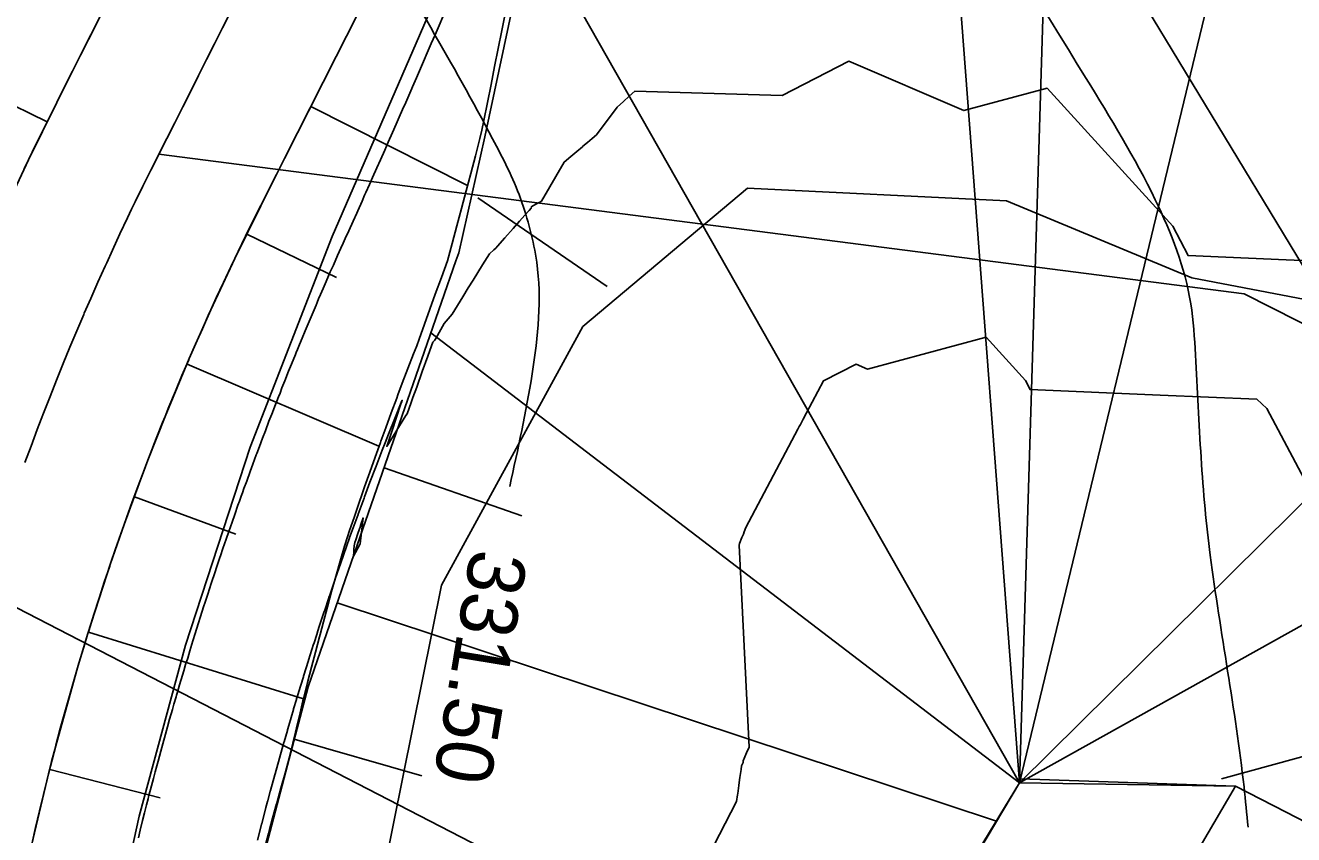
# Model space of a CAD drawing. Extents: x -564037 to -563827, y -1163561 to -1163412.
# Drawn here: x -563863.65 to -563852.55, y -1163500.35 to -1163493.27 of the extents above; entities that cross this region are included whole.
import ezdxf

# ---------------------------------------------------------------- set-up
doc = ezdxf.new("R2010")
doc.units = 0
for name, color, linetype in [('5', 7, 'Continuous'), ('_popis staničení PH4', 7, 'Continuous'), ('Default', 7, 'Continuous'), ('Line', 7, 'Continuous'), ('Vrstva 24', 7, 'Continuous'), ('Vrstva 25', 7, 'Continuous'), ('Vrstva 26', 7, 'Continuous')]:
    doc.layers.add(name, color=color, linetype=linetype)

msp = doc.modelspace()

# ---------------------------------------------------------------- linework, layer by layer
for points in [[(-563865.785, -1163501.206), (-563865.619, -1163500.343), (-563865.574, -1163500.129), (-563865.385, -1163499.33), (-563865.317, -1163499.063), (-563865.111, -1163498.327), (-563865.015, -1163498.009), (-563864.797, -1163497.335), (-563864.669, -1163496.968), (-563864.528, -1163496.58), (-563864.443, -1163496.357), (-563864.28, -1163495.943), (-563864.051, -1163495.394), (-563863.848, -1163494.935), (-563863.62, -1163494.448), (-563863.373, -1163493.946), (-563863.165, -1163493.533), (-563862.713, -1163492.641), (-563862.262, -1163491.749), (-563861.987, -1163491.206), (-563861.81, -1163490.857), (-563861.359, -1163489.964), (-563861.279, -1163489.807)], [(-563863.62, -1163500.557), (-563863.446, -1163499.819), (-563863.383, -1163499.573), (-563863.193, -1163498.893), (-563863.104, -1163498.599), (-563862.903, -1163497.978), (-563862.785, -1163497.638), (-563862.654, -1163497.28), (-563862.576, -1163497.075), (-563862.426, -1163496.692), (-563862.214, -1163496.186), (-563862.026, -1163495.761), (-563861.817, -1163495.312), (-563861.589, -1163494.849), (-563861.38, -1163494.436), (-563860.928, -1163493.544), (-563860.477, -1163492.652), (-563860.202, -1163492.109), (-563860.026, -1163491.76), (-563859.574, -1163490.867), (-563859.495, -1163490.71)], [(-563863.653, -1163497.097), (-563863.599, -1163496.952), (-563863.545, -1163496.807), (-563863.51, -1163496.716), (-563863.489, -1163496.663), (-563863.433, -1163496.518), (-563863.376, -1163496.374), (-563863.353, -1163496.317), (-563863.318, -1163496.231), (-563863.259, -1163496.088), (-563863.199, -1163495.945), (-563863.138, -1163495.802), (-563863.133, -1163495.79), (-563863.076, -1163495.66), (-563863.014, -1163495.519), (-563862.95, -1163495.377), (-563862.937, -1163495.348), (-563862.886, -1163495.237), (-563862.821, -1163495.096), (-563862.755, -1163494.956), (-563862.719, -1163494.88), (-563862.688, -1163494.816), (-563862.62, -1163494.677), (-563862.552, -1163494.538), (-563862.482, -1163494.4), (-563862.481, -1163494.397), (-563862.412, -1163494.262), (-563862.342, -1163494.123), (-563862.272, -1163493.985), (-563862.202, -1163493.847), (-563862.133, -1163493.709), (-563862.063, -1163493.571), (-563861.993, -1163493.433), (-563861.923, -1163493.294), (-563861.853, -1163493.156)], [(-563863.593, -1163500.434), (-563863.56, -1163500.289), (-563863.526, -1163500.144), (-563863.491, -1163500), (-563863.455, -1163499.856), (-563863.446, -1163499.819), (-563863.419, -1163499.711), (-563863.383, -1163499.573), (-563863.381, -1163499.568), (-563863.343, -1163499.424), (-563863.304, -1163499.281), (-563863.264, -1163499.137), (-563863.223, -1163498.995), (-563863.193, -1163498.893), (-563863.181, -1163498.852), (-563863.138, -1163498.71), (-563863.104, -1163498.599), (-563863.094, -1163498.567), (-563863.05, -1163498.426), (-563863.004, -1163498.284), (-563862.958, -1163498.143), (-563862.911, -1163498.002), (-563862.903, -1163497.978), (-563862.863, -1163497.861), (-563862.814, -1163497.721), (-563862.785, -1163497.638), (-563862.764, -1163497.581), (-563862.714, -1163497.441), (-563862.662, -1163497.301), (-563862.61, -1163497.162), (-563862.576, -1163497.075), (-563862.557, -1163497.023), (-563862.503, -1163496.885), (-563862.448, -1163496.747), (-563862.426, -1163496.692), (-563862.392, -1163496.609), (-563862.335, -1163496.472), (-563862.278, -1163496.334), (-563862.219, -1163496.198), (-563862.214, -1163496.186), (-563862.16, -1163496.061), (-563862.1, -1163495.925), (-563862.039, -1163495.79), (-563862.026, -1163495.761), (-563861.978, -1163495.654), (-563861.915, -1163495.52), (-563861.852, -1163495.385), (-563861.817, -1163495.312), (-563861.787, -1163495.251), (-563861.722, -1163495.117), (-563861.657, -1163494.984), (-563861.59, -1163494.851), (-563861.589, -1163494.849), (-563861.52, -1163494.713), (-563861.45, -1163494.575), (-563861.38, -1163494.436), (-563861.31, -1163494.299), (-563861.24, -1163494.16), (-563861.17, -1163494.022), (-563861.1, -1163493.884), (-563861.031, -1163493.746), (-563860.961, -1163493.608), (-563860.928, -1163493.544), (-563860.891, -1163493.47), (-563860.821, -1163493.331), (-563860.751, -1163493.193)], [(-563861.556, -1163500.472), (-563861.521, -1163500.34), (-563861.512, -1163500.306), (-563861.485, -1163500.208), (-563861.45, -1163500.081), (-563861.449, -1163500.077), (-563861.412, -1163499.946), (-563861.374, -1163499.815), (-563861.34, -1163499.683), (-563861.309, -1163499.55), (-563861.286, -1163499.455), (-563861.277, -1163499.417), (-563861.245, -1163499.285), (-563861.219, -1163499.182), (-563861.212, -1163499.152), (-563861.179, -1163499.019), (-563861.145, -1163498.887), (-563861.111, -1163498.754), (-563861.076, -1163498.622), (-563861.07, -1163498.599), (-563861.041, -1163498.489), (-563861.005, -1163498.357), (-563860.984, -1163498.279), (-563860.969, -1163498.225), (-563860.932, -1163498.092), (-563860.895, -1163497.96), (-563860.857, -1163497.828), (-563860.83, -1163497.746), (-563860.814, -1163497.698), (-563860.769, -1163497.568), (-563860.725, -1163497.438), (-563860.707, -1163497.386), (-563860.68, -1163497.308), (-563860.634, -1163497.179), (-563860.588, -1163497.049), (-563860.541, -1163496.92), (-563860.537, -1163496.909), (-563860.494, -1163496.791), (-563860.446, -1163496.661), (-563860.398, -1163496.532), (-563860.388, -1163496.505), (-563860.35, -1163496.403), (-563860.301, -1163496.274), (-563860.251, -1163496.146), (-563860.224, -1163496.075), (-563860.201, -1163496.017), (-563860.155, -1163495.886), (-563860.109, -1163495.755), (-563860.062, -1163495.624), (-563860.061, -1163495.622), (-563860.008, -1163495.478), (-563859.954, -1163495.332), (-563859.913, -1163495.179), (-563859.872, -1163495.026), (-563859.831, -1163494.873), (-563859.791, -1163494.72), (-563859.751, -1163494.567), (-563859.71, -1163494.414), (-563859.671, -1163494.26), (-563859.655, -1163494.189), (-563859.637, -1163494.104), (-563859.605, -1163493.946), (-563859.573, -1163493.789), (-563859.542, -1163493.631), (-563859.51, -1163493.474), (-563859.479, -1163493.316), (-563859.451, -1163493.171)], [(-563863.658, -1163494.527), (-563863.62, -1163494.448), (-563863.589, -1163494.382), (-563863.518, -1163494.237), (-563863.447, -1163494.092), (-563863.374, -1163493.948), (-563863.373, -1163493.946), (-563863.305, -1163493.81), (-563863.235, -1163493.672), (-563863.165, -1163493.533), (-563863.095, -1163493.396), (-563863.025, -1163493.257)], [(-563851.978, -1163495.349), (-563852.615, -1163495.322), (-563853.472, -1163495.285), (-563853.605, -1163495.027), (-563854.706, -1163493.822), (-563855.435, -1163494.017), (-563856.443, -1163493.586), (-563857.024, -1163493.885), (-563858.314, -1163493.847), (-563858.363, -1163493.892), (-563858.414, -1163493.938), (-563858.468, -1163493.988), (-563858.651, -1163494.229), (-563858.689, -1163494.261), (-563858.73, -1163494.296), (-563858.769, -1163494.329), (-563858.774, -1163494.333), (-563858.822, -1163494.374), (-563858.875, -1163494.418), (-563858.933, -1163494.467), (-563859.131, -1163494.809), (-563859.152, -1163494.82), (-563859.176, -1163494.834), (-563859.201, -1163494.847), (-563859.208, -1163494.851), (-563859.22, -1163494.858), (-563859.223, -1163494.872), (-563859.239, -1163494.89), (-563859.277, -1163494.933), (-563859.323, -1163494.985), (-563859.38, -1163495.049), (-563859.452, -1163495.13), (-563859.516, -1163495.202), (-563859.532, -1163495.22), (-563859.55, -1163495.236), (-563859.588, -1163495.27), (-563859.647, -1163495.365), (-563859.731, -1163495.502), (-563859.772, -1163495.568), (-563859.819, -1163495.646), (-563859.914, -1163495.799), (-563859.984, -1163495.881), (-563860.055, -1163496.01), (-563860.068, -1163496.027), (-563860.083, -1163496.044), (-563860.108, -1163496.116), (-563860.127, -1163496.166), (-563860.175, -1163496.301), (-563860.224, -1163496.436), (-563860.257, -1163496.528), (-563860.272, -1163496.571), (-563860.308, -1163496.67), (-563860.318, -1163496.685), (-563860.486, -1163496.955), (-563860.463, -1163496.887), (-563860.451, -1163496.852), (-563860.436, -1163496.807), (-563860.403, -1163496.707), (-563860.359, -1163496.574), (-563860.358, -1163496.571), (-563860.351, -1163496.551), (-563860.359, -1163496.571), (-563860.359, -1163496.571), (-563860.416, -1163496.71), (-563860.416, -1163496.71), (-563860.471, -1163496.849), (-563860.471, -1163496.849), (-563860.5, -1163496.924), (-563860.501, -1163496.925), (-563860.525, -1163496.989), (-563860.526, -1163496.989), (-563860.579, -1163497.128), (-563860.58, -1163497.129), (-563860.633, -1163497.268), (-563860.633, -1163497.269), (-563860.681, -1163497.397), (-563860.681, -1163497.397), (-563860.685, -1163497.409), (-563860.685, -1163497.409), (-563860.737, -1163497.549), (-563860.737, -1163497.55), (-563860.788, -1163497.69), (-563860.788, -1163497.69), (-563860.811, -1163497.753), (-563860.811, -1163497.754), (-563860.838, -1163497.831), (-563860.838, -1163497.832), (-563860.888, -1163497.972), (-563860.888, -1163497.973), (-563860.936, -1163498.113), (-563860.937, -1163498.115), (-563860.985, -1163498.255), (-563860.985, -1163498.255), (-563860.992, -1163498.276), (-563860.993, -1163498.279), (-563861.032, -1163498.397), (-563861.033, -1163498.4), (-563861.079, -1163498.539), (-563861.079, -1163498.54), (-563861.095, -1163498.59), (-563861.096, -1163498.593), (-563861.125, -1163498.681), (-563861.126, -1163498.685), (-563861.17, -1163498.824), (-563861.171, -1163498.828), (-563861.214, -1163498.966), (-563861.216, -1163498.971), (-563861.258, -1163499.109), (-563861.259, -1163499.111), (-563861.275, -1163499.164), (-563861.276, -1163499.168), (-563861.301, -1163499.252), (-563861.303, -1163499.258), (-563861.343, -1163499.396), (-563861.344, -1163499.397), (-563861.355, -1163499.435), (-563861.356, -1163499.439), (-563861.385, -1163499.539), (-563861.387, -1163499.546), (-563861.426, -1163499.683), (-563861.464, -1163499.82), (-563861.466, -1163499.827), (-563861.504, -1163499.964), (-563861.505, -1163499.971), (-563861.528, -1163500.056), (-563861.529, -1163500.061), (-563861.543, -1163500.113), (-563861.544, -1163500.116), (-563861.58, -1163500.254), (-563861.582, -1163500.26), (-563861.589, -1163500.286), (-563861.589, -1163500.287), (-563861.618, -1163500.4)], [(-563851.082, -1163505.728), (-563849.948, -1163501.531), (-563849.628, -1163500.347), (-563850.165, -1163499.681), (-563852.128, -1163495.731), (-563853.44, -1163495.48), (-563855.061, -1163494.806), (-563857.328, -1163494.696), (-563858.771, -1163495.906), (-563860.007, -1163498.17), (-563860.512, -1163500.673), (-563860.896, -1163502.23)], [(-563859.058, -1163503.231), (-563857.424, -1163500.06), (-563857.416, -1163500.003), (-563857.414, -1163499.991), (-563857.404, -1163499.921), (-563857.401, -1163499.894), (-563857.395, -1163499.851), (-563857.385, -1163499.781), (-563857.38, -1163499.748), (-563857.366, -1163499.72), (-563857.367, -1163499.709), (-563857.367, -1163499.705), (-563857.337, -1163499.637), (-563857.314, -1163499.585), (-563857.403, -1163497.819), (-563857.398, -1163497.805), (-563857.377, -1163497.753), (-563857.365, -1163497.722), (-563857.357, -1163497.702), (-563857.342, -1163497.665), (-563856.887, -1163496.804), (-563856.887, -1163496.803), (-563856.885, -1163496.799), (-563856.875, -1163496.781), (-563856.866, -1163496.763), (-563856.86, -1163496.752), (-563856.856, -1163496.745), (-563856.847, -1163496.728), (-563856.842, -1163496.718), (-563856.812, -1163496.661), (-563856.664, -1163496.381), (-563856.379, -1163496.234), (-563856.277, -1163496.278), (-563855.24, -1163496), (-563854.896, -1163496.377), (-563854.855, -1163496.458), (-563853.717, -1163496.506), (-563852.871, -1163496.541), (-563852.783, -1163496.623), (-563852.407, -1163497.332)], [(-563855.984, -1163506.959), (-563857.031, -1163504.7), (-563857.031, -1163504.7), (-563856.418, -1163503.019), (-563856.418, -1163503.019), (-563855.805, -1163501.338), (-563854.949, -1163499.897), (-563853.059, -1163499.927), (-563853.059, -1163499.927), (-563852.615, -1163500.156), (-563851.726, -1163500.614), (-563850.837, -1163501.073), (-563850.62, -1163501.184), (-563850.566, -1163501.212), (-563849.948, -1163501.531), (-563849.059, -1163501.989), (-563848.632, -1163503.326), (-563848.683, -1163504.7), (-563848.816, -1163505.479), (-563849.057, -1163506.682), (-563849.057, -1163506.682)], [(-563854.345, -1163502.122), (-563853.059, -1163499.927), (-563853.059, -1163499.927), (-563854.941, -1163499.862), (-563854.943, -1163499.866), (-563854.945, -1163499.871), (-563854.945, -1163499.872), (-563854.945, -1163499.872), (-563854.946, -1163499.874), (-563854.947, -1163499.877), (-563854.947, -1163499.882), (-563854.948, -1163499.885), (-563854.948, -1163499.887), (-563854.949, -1163499.892), (-563854.949, -1163499.893), (-563854.949, -1163499.897), (-563855.795, -1163501.288)]]:
    msp.add_lwpolyline(points)
for points in [[(-563864.657, -1163510.241), (-563863.634, -1163509.902), (-563862.371, -1163510.364), (-563856.258, -1163509.872), (-563849.971, -1163509.495), (-563846.657, -1163503.058), (-563846.814, -1163502.626), (-563847.162, -1163502.341), (-563848.492, -1163499.244), (-563850.901, -1163494.112), (-563854.114, -1163491.532), (-563858.451, -1163490.091), (-563858.61, -1163489.95), (-563858.72, -1163489.955), (-563860.965, -1163495.118), (-563861.68, -1163496.963), (-563862.247, -1163498.693), (-563862.652, -1163500.191), (-563862.88, -1163501.229), (-563863.177, -1163502.77), (-563863.416, -1163504.013), (-563864.472, -1163509.23)], [(-563860.775, -1163497.874), (-563860.774, -1163497.856), (-563860.772, -1163497.824), (-563860.764, -1163497.796), (-563860.757, -1163497.773), (-563860.738, -1163497.717), (-563860.717, -1163497.654), (-563860.715, -1163497.648), (-563860.693, -1163497.58), (-563860.72, -1163497.806), (-563860.723, -1163497.812), (-563860.778, -1163497.915)]]:
    msp.add_lwpolyline(points, close=True)
at = {"layer": '5'}
for p, q in [((-563856.14, -1163489.312), (-563850.828, -1163498.085)), ((-563871.424, -1163494.398), (-563841.172, -1163509.993))]:
    msp.add_line(p, q, dxfattribs=at)
at = {"layer": '_popis staničení PH4'}
msp.add_lwpolyline([(-563862.481, -1163494.397), (-563852.983, -1163495.62), (-563837.783, -1163503.311)], dxfattribs=at)
at = {"layer": 'Default'}
for points in [[(-563861.871, -1163501.708), (-563861.355, -1163499.743), (-563861.175, -1163499.057), (-563860.744, -1163497.818), (-563860.132, -1163496.055), (-563859.88, -1163495.331), (-563859.856, -1163495.261), (-563859.628, -1163494.247), (-563858.554, -1163489.211), (-563856.89, -1163488.106), (-563853.44, -1163488.662), (-563853.44, -1163488.662), (-563852.435, -1163488.408)], [(-563859.996, -1163493.197), (-563860.028, -1163493.272), (-563860.063, -1163493.354), (-563860.096, -1163493.43), (-563860.131, -1163493.511), (-563860.165, -1163493.588), (-563860.199, -1163493.668), (-563860.227, -1163493.731), (-563860.26, -1163493.809), (-563860.267, -1163493.824), (-563860.302, -1163493.904), (-563860.329, -1163493.966), (-563860.336, -1163493.981), (-563860.368, -1163494.054), (-563860.404, -1163494.136), (-563860.436, -1163494.209), (-563860.473, -1163494.292), (-563860.504, -1163494.364), (-563860.541, -1163494.448), (-563860.573, -1163494.519), (-563860.61, -1163494.603), (-563860.637, -1163494.663), (-563860.669, -1163494.735), (-563860.68, -1163494.758), (-563860.702, -1163494.809), (-563860.74, -1163494.894), (-563860.749, -1163494.914), (-563860.78, -1163494.983), (-563860.819, -1163495.068), (-563860.85, -1163495.137), (-563860.867, -1163495.176), (-563860.887, -1163495.221), (-563860.901, -1163495.252), (-563860.916, -1163495.286), (-563860.953, -1163495.368), (-563860.98, -1163495.429), (-563861.016, -1163495.512), (-563861.043, -1163495.574), (-563861.065, -1163495.625), (-563861.082, -1163495.664), (-563861.095, -1163495.695), (-563861.105, -1163495.718), (-563861.14, -1163495.8), (-563861.166, -1163495.862), (-563861.2, -1163495.945), (-563861.226, -1163496.007), (-563861.249, -1163496.064), (-563861.267, -1163496.106), (-563861.278, -1163496.132), (-563861.286, -1163496.152), (-563861.319, -1163496.235), (-563861.345, -1163496.298), (-563861.378, -1163496.38), (-563861.403, -1163496.443), (-563861.42, -1163496.488), (-563861.434, -1163496.522), (-563861.449, -1163496.56), (-563861.46, -1163496.589), (-563861.492, -1163496.672), (-563861.517, -1163496.735), (-563861.548, -1163496.818), (-563861.573, -1163496.882), (-563861.601, -1163496.957), (-563861.623, -1163497.016), (-563861.626, -1163497.023), (-563861.628, -1163497.028), (-563861.658, -1163497.111), (-563861.682, -1163497.175), (-563861.712, -1163497.258), (-563861.736, -1163497.322), (-563861.749, -1163497.36), (-563861.759, -1163497.389), (-563861.776, -1163497.434), (-563861.788, -1163497.47), (-563861.817, -1163497.552), (-563861.84, -1163497.617), (-563861.869, -1163497.7), (-563861.891, -1163497.765), (-563861.92, -1163497.848), (-563861.942, -1163497.913), (-563861.946, -1163497.926), (-563861.949, -1163497.936), (-563861.973, -1163498.006), (-563861.992, -1163498.062), (-563862.019, -1163498.145), (-563862.041, -1163498.21), (-563862.05, -1163498.24), (-563862.058, -1163498.264), (-563862.075, -1163498.318), (-563862.089, -1163498.359), (-563862.115, -1163498.443), (-563862.136, -1163498.508), (-563862.162, -1163498.592), (-563862.183, -1163498.657), (-563862.209, -1163498.742), (-563862.228, -1163498.807), (-563862.238, -1163498.839), (-563862.246, -1163498.864), (-563862.262, -1163498.917), (-563862.274, -1163498.956), (-563862.299, -1163499.042), (-563862.318, -1163499.106), (-563862.325, -1163499.13), (-563862.33, -1163499.147), (-563862.348, -1163499.21), (-563862.361, -1163499.256), (-563862.386, -1163499.342), (-563862.404, -1163499.407), (-563862.422, -1163499.471), (-563862.446, -1163499.557), (-563862.464, -1163499.622), (-563862.487, -1163499.708), (-563862.498, -1163499.748), (-563862.512, -1163499.802), (-563862.519, -1163499.826), (-563862.528, -1163499.859), (-563862.545, -1163499.924), (-563862.567, -1163500.01), (-563862.57, -1163500.022), (-563862.574, -1163500.038), (-563862.588, -1163500.091), (-563862.606, -1163500.162), (-563862.623, -1163500.227), (-563862.644, -1163500.313), (-563862.66, -1163500.379)]]:
    msp.add_lwpolyline(points, dxfattribs=at)
at = {"layer": 'Line'}
for p, q in [((-563855.832, -1163488.276), (-563854.949, -1163499.897)), ((-563854.949, -1163499.897), (-563854.598, -1163488.475)), ((-563854.949, -1163499.897), (-563852.219, -1163488.602)), ((-563863.457, -1163494.115), (-563867.593, -1163492.106)), ((-563854.949, -1163499.897), (-563859.159, -1163492.49)), ((-563848.377, -1163493.402), (-563854.949, -1163499.897)), ((-563861.15, -1163493.982), (-563859.778, -1163494.673)), ((-563858.558, -1163495.555), (-563859.689, -1163494.781)), ((-563860.927, -1163495.476), (-563861.711, -1163495.099)), ((-563847.374, -1163495.674), (-563854.949, -1163499.897)), ((-563860.099, -1163495.962), (-563854.949, -1163499.897)), ((-563862.233, -1163496.234), (-563860.554, -1163496.954)), ((-563859.304, -1163497.561), (-563860.509, -1163497.143)), ((-563861.808, -1163497.722), (-563862.695, -1163497.396)), ((-563846.885, -1163498.126), (-563853.181, -1163499.864)), ((-563860.92, -1163498.323), (-563855.149, -1163500.234)), ((-563863.096, -1163498.579), (-563861.215, -1163499.163)), ((-563860.18, -1163499.837), (-563861.295, -1163499.515)), ((-563862.469, -1163500.028), (-563863.435, -1163499.782))]:
    msp.add_line(p, q, dxfattribs=at)
at = {"layer": 'Vrstva 24'}
for points in [[(-563834.56, -1163494.639), (-563836.366, -1163491.682), (-563837.263, -1163490.402), (-563838.091, -1163489.323), (-563838.932, -1163488.255), (-563840.679, -1163486.176), (-563843.599, -1163482.931), (-563845.377, -1163480.993), (-563847.69, -1163478.523), (-563848.871, -1163477.312), (-563850.082, -1163476.13), (-563853.183, -1163473.259), (-563856.324, -1163470.434), (-563856.74, -1163470.064), (-563856.896, -1163469.927), (-563857.179, -1163469.672), (-563858.782, -1163468.194), (-563860.374, -1163466.704), (-563861.969, -1163465.217), (-563862.806, -1163464.448)], [(-563852.947, -1163500.287), (-563852.983, -1163499.934), (-563853.278, -1163497.907), (-563853.324, -1163497.501), (-563853.384, -1163496.604), (-563853.408, -1163496.155), (-563853.449, -1163495.707), (-563853.76, -1163494.797), (-563854.364, -1163493.737), (-563856.816, -1163489.636), (-563859.313, -1163485.439), (-563859.915, -1163484.694), (-563860.397, -1163484.207), (-563862.509, -1163482.09), (-563867.011, -1163477.664), (-563868.116, -1163476.702), (-563871.116, -1163474.41), (-563872.986, -1163473.06), (-563873.689, -1163472.566), (-563878.103, -1163469.411), (-563878.316, -1163469.26)], [(-563840.258, -1163509.873), (-563839.896, -1163508.143), (-563839.904, -1163507.091), (-563840.452, -1163504.683), (-563840.841, -1163503.06), (-563841.044, -1163502.221), (-563841.512, -1163500.521), (-563841.78, -1163499.679), (-563842.064, -1163498.842), (-563842.395, -1163498.068), (-563843.845, -1163495.39), (-563845.853, -1163491.78), (-563846.807, -1163490.032), (-563847.876, -1163488.404), (-563852.123, -1163483.19), (-563853.868, -1163481.341), (-563857.18, -1163478.245), (-563858.504, -1163477.011), (-563860.386, -1163475.26)]]:
    msp.add_spline(points, degree=3, dxfattribs=at)
at = {"layer": 'Vrstva 26'}
for points in [[(-563838.029, -1163497.163), (-563838.58, -1163496.19), (-563840.28, -1163493.165), (-563841.199, -1163491.578), (-563841.674, -1163490.793), (-563842.159, -1163490.013), (-563843.649, -1163487.993), (-563844.702, -1163486.757), (-563850.461, -1163480.038), (-563851.089, -1163479.371), (-563851.956, -1163478.574), (-563857.613, -1163473.501), (-563859.731, -1163471.636), (-563864.022, -1163468.083), (-563864.562, -1163467.631), (-563865.045, -1163467.216), (-563865.679, -1163466.68)], [(-563859.41, -1163497.306), (-563859.213, -1163496.32), (-563859.173, -1163495.343), (-563859.23, -1163495.062), (-563859.315, -1163494.786), (-563859.559, -1163494.264), (-563860.664, -1163492.33), (-563861.767, -1163490.395), (-563863.612, -1163487.077), (-563864.619, -1163485.435), (-563865.167, -1163484.642), (-563865.744, -1163483.864), (-563868.01, -1163481.46), (-563871.348, -1163478.665), (-563874.529, -1163476.131), (-563879.25, -1163472.365), (-563881.038, -1163471.025), (-563881.839, -1163470.479), (-563883.542, -1163469.415), (-563886.341, -1163467.718)], [(-563846.143, -1163505.119), (-563846.16, -1163504.298), (-563846.784, -1163499.435), (-563846.859, -1163499.141), (-563847.15, -1163498.47), (-563847.685, -1163497.291), (-563847.809, -1163497.032), (-563850.257, -1163492.396), (-563853.06, -1163487.093), (-563853.131, -1163486.997), (-563856.933, -1163483.04), (-563859.434, -1163480.56), (-563863.484, -1163476.533), (-563865.168, -1163474.917), (-563866.123, -1163474.143), (-563868.988, -1163472.112)]]:
    msp.add_spline(points, degree=3, dxfattribs=at)

# ---------------------------------------------------------------- texts
at = {"layer": 'Vrstva 25'}
msp.add_text('331.50', height=0.5, rotation=260.6689, dxfattribs=at).set_placement((-563859.746, -1163497.839))

doc.saveas('drawing.dxf')
